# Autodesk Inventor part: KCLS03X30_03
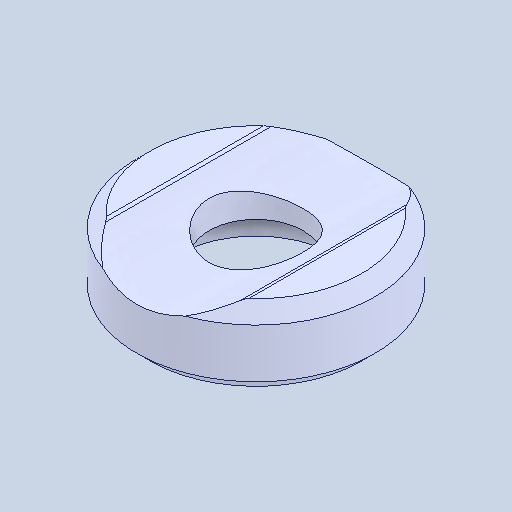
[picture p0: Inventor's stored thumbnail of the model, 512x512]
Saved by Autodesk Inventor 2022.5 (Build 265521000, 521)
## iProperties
Created: 2024-08
Part Number: KCLS03X30_03
Material: 一般
Document SubType Name: Modeling
Designer: ImaoCorp
Density: 1 g/cm^3
Appearance: 既定
Author: ImaoCorp
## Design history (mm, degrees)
feature "KCLS03X30_03"
node "ソリッド1"
